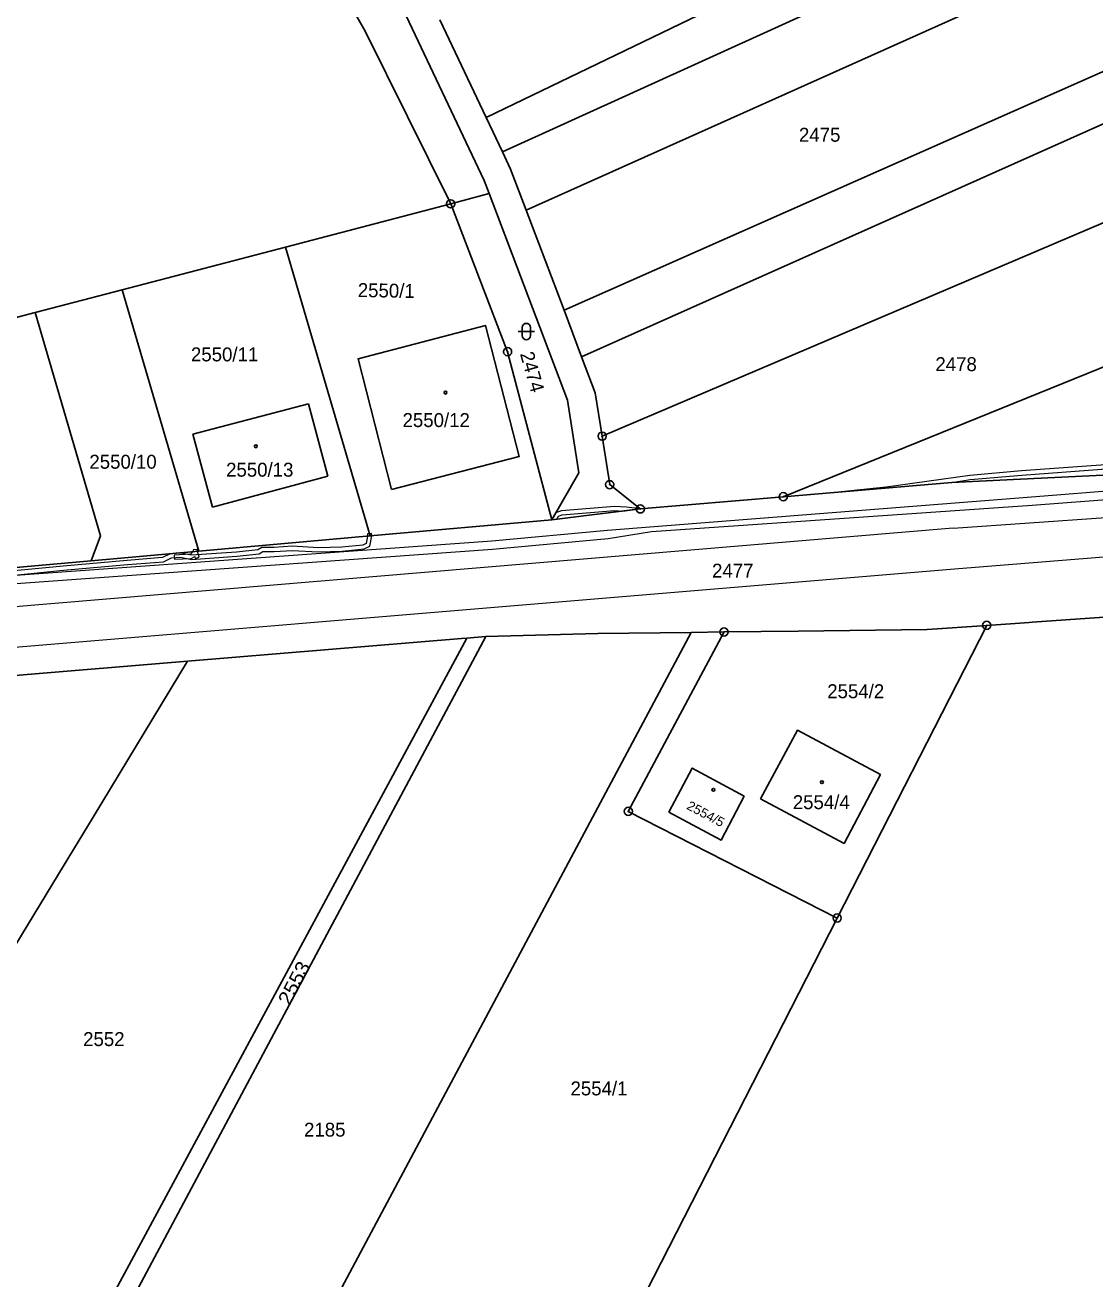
# Model space of a CAD drawing. Extents: x -606517 to -602431, y -1183120 to -1179397.
# Drawn here: x -605132.4 to -605001.8, y -1181010.4 to -1180857.3 of the extents above; entities that cross this region are included whole.
import ezdxf
from ezdxf.enums import TextEntityAlignment as Align

# ---------------------------------------------------------------- set-up
doc = ezdxf.new("R2010")
doc.units = 0
doc.header["$LTSCALE"] = 0.68
for name, color, linetype, lineweight in [('1', 7, 'Continuous', 25), ('13', 7, 'Continuous', 13), ('3', 7, 'Continuous', 25), ('4', 7, 'Continuous', 13), ('5', 7, 'Continuous', 25), ('8', 7, 'Continuous', 25)]:
    doc.layers.add(name, color=color, linetype=linetype, lineweight=lineweight)
doc.layers.add('2', color=7, linetype='Continuous')

msp = doc.modelspace()

# ---------------------------------------------------------------- linework, layer by layer
at = {"layer": '1'}
for p, q in [((-605076.11, -1180868.57), (-604959.12, -1180811.92)), ((-605074.12, -1180872.77), (-604955.31, -1180818.73)), ((-604951.69, -1180826.26), (-605071.22, -1180879.91)), ((-605101.48, -1180839.48), (-605090.87, -1180858.03)), ((-605066.61, -1180892.1), (-604946.99, -1180839.11)), ((-604945.04, -1180844.43), (-605064.46, -1180897.79)), ((-605076.35, -1180876.25), (-605090.81, -1180845.71)), ((-605081.76, -1180856.63), (-605076.11, -1180868.57)), ((-605061.96, -1180907.49), (-604942.1, -1180856.39)), ((-605090.87, -1180858.03), (-605080.53, -1180878.86)), ((-605074.12, -1180872.77), (-605076.11, -1180868.57)), ((-605073.13, -1180874.88), (-605074.12, -1180872.77)), ((-604937.14, -1180873.25), (-605039.85, -1180914.88)), ((-605071.22, -1180879.91), (-605073.13, -1180874.88)), ((-605075.74, -1180877.86), (-605076.35, -1180876.25)), ((-605080.44, -1180879.12), (-605075.74, -1180877.86)), ((-605066.19, -1180903.1), (-605075.74, -1180877.86)), ((-605080.53, -1180878.86), (-605080.44, -1180879.12)), ((-605080.44, -1180879.12), (-605073.5, -1180897.18)), ((-605071.22, -1180879.91), (-605066.61, -1180892.1)), ((-605100.61, -1180884.4), (-605120.54, -1180889.62)), ((-605120.54, -1180889.62), (-605131.18, -1180892.4)), ((-605131.18, -1180892.4), (-605153.68, -1180898.29)), ((-605064.46, -1180897.79), (-605066.61, -1180892.1)), ((-605073.5, -1180897.18), (-605068.11, -1180917.7)), ((-605064.46, -1180897.79), (-605062.79, -1180902.2)), ((-605062.79, -1180902.2), (-605061.96, -1180907.49)), ((-605097.8, -1180903.56), (-605111.9, -1180907.26)), ((-605095.45, -1180912.39), (-605097.8, -1180903.56)), ((-605064.8, -1180911.96), (-605066.19, -1180903.1)), ((-605111.9, -1180907.26), (-605109.53, -1180916.14)), ((-605061.03, -1180913.4), (-605061.96, -1180907.49)), ((-604991.55, -1180911.78), (-605019.29, -1180913.13)), ((-605109.53, -1180916.14), (-605095.45, -1180912.39)), ((-605068.11, -1180917.7), (-605064.8, -1180911.96)), ((-605057.3, -1180916.37), (-605061.03, -1180913.4)), ((-605019.29, -1180913.13), (-605039.85, -1180914.88)), ((-605039.85, -1180914.88), (-605057.3, -1180916.37)), ((-605068.11, -1180917.7), (-605057.3, -1180916.37)), ((-605090.27, -1180919.67), (-605068.11, -1180917.7)), ((-605124.32, -1180922.7), (-605111.18, -1180921.53)), ((-605148.55, -1180924.86), (-605124.32, -1180922.7)), ((-605015.01, -1180930.59), (-605009.83, -1180930.23)), ((-605009.83, -1180930.23), (-605009.45, -1180930.2)), ((-605009.45, -1180930.2), (-604990.65, -1180928.92)), ((-605116.76, -1181054.62), (-605051.07, -1180931.45)), ((-605062.49, -1180931.59), (-605076.15, -1180931.95)), ((-605051.07, -1180931.45), (-605062.49, -1180931.59)), ((-605051.07, -1180931.45), (-605047.08, -1180931.4)), ((-605047.08, -1180931.4), (-605038.03, -1180931.29)), ((-605038.03, -1180931.29), (-605022.3, -1180931.09)), ((-605033.27, -1180966.33), (-605015.01, -1180930.59)), ((-605022.3, -1180931.09), (-605015.01, -1180930.59)), ((-605078.46, -1180932.14), (-605138.39, -1181043.38)), ((-605076.15, -1180931.95), (-605136.19, -1181044.52)), ((-605112.56, -1180934.97), (-605079.11, -1180932.19)), ((-605079.11, -1180932.19), (-605078.46, -1180932.14)), ((-605076.21, -1180931.95), (-605078.46, -1180932.14)), ((-605076.15, -1180931.95), (-605076.21, -1180931.95)), ((-605133.61, -1180936.72), (-605112.56, -1180934.97)), ((-605112.56, -1180934.97), (-605124.1, -1180954)), ((-605124.1, -1180954), (-605128.32, -1180960.97)), ((-605128.32, -1180960.97), (-605169.43, -1181028.73)), ((-605085.89, -1181069.32), (-605033.27, -1180966.33))]:
    msp.add_line(p, q, dxfattribs=at)
for points in [[(-605080.44, -1180879.12), (-605100.61, -1180884.4), (-605090.27, -1180919.67)], [(-605120.54, -1180889.62), (-605111.18, -1180921.53), (-605090.27, -1180919.67)], [(-605131.18, -1180892.4), (-605123.19, -1180919.65), (-605124.32, -1180922.7)], [(-605047.08, -1180931.4), (-605058.76, -1180953.31), (-605033.27, -1180966.33)]]:
    msp.add_lwpolyline(points, dxfattribs=at)
for points in [[(-605087.65, -1180914), (-605091.75, -1180898.03), (-605076.19, -1180893.99), (-605072.09, -1180909.99)], [(-605042.63, -1180951.79), (-605038.11, -1180943.39), (-605027.98, -1180948.81), (-605032.43, -1180957.21)], [(-605053.8, -1180953.39), (-605050.96, -1180948.03), (-605044.62, -1180951.45), (-605047.42, -1180956.81)]]:
    msp.add_lwpolyline(points, close=True, dxfattribs=at)
at = {"layer": '13'}
for points in [[(-604965.16, -1180914.07), (-604966.44, -1180913.52), (-604975.42, -1180911.48), (-604982.15, -1180910.49), (-604988.28, -1180910.43), (-604999.37, -1180910.91), (-605010.75, -1180911.74), (-605017.08, -1180912.29), (-605027.29, -1180913.7), (-605032.77, -1180914.28), (-605019.29, -1180913.13), (-605017.02, -1180912.79), (-605010.71, -1180912.24), (-604999.35, -1180911.41), (-604988.28, -1180910.93), (-604982.19, -1180910.99), (-604975.52, -1180911.98), (-604966.58, -1180914), (-604965.71, -1180914.39)], [(-605057.3, -1180916.37), (-605058.97, -1180916.17), (-605060.43, -1180916.08), (-605066.93, -1180916.61), (-605067.63, -1180916.86), (-605068.11, -1180917.7), (-605067.49, -1180917.62), (-605067.29, -1180917.27), (-605066.83, -1180917.11), (-605060.43, -1180916.58), (-605059.49, -1180916.64)], [(-605090.58, -1180919.43), (-605090.58, -1180919.7), (-605090.27, -1180919.67), (-605090.35, -1180919.41)], [(-605090.35, -1180919.41), (-605090.27, -1180919.67), (-605090.07, -1180919.65), (-605090.09, -1180919.39)], [(-605111.35, -1180921.55), (-605111.92, -1180921.6), (-605112.19, -1180921.9), (-605114.18, -1180922), (-605114.16, -1180922.5), (-605112.13, -1180922.41), (-605111.68, -1180922.19), (-605111.62, -1180922.41), (-605111.14, -1180922.27)], [(-605111.92, -1180921.6), (-605111.35, -1180921.55), (-605111.37, -1180921.34), (-605111.87, -1180921.35)]]:
    msp.add_lwpolyline(points, close=True, dxfattribs=at)
for points in [[(-604998.29, -1180914.05), (-605009.54, -1180914.93), (-605061.31, -1180919), (-605075.44, -1180920.3), (-605155.59, -1180926.08), (-605179.81, -1180927.64), (-605194.41, -1180928.93), (-605194.33, -1180929.71), (-605155.53, -1180927.08), (-605075.34, -1180921.3), (-605061.23, -1180920), (-605055.93, -1180919.13), (-605009.47, -1180915.93), (-604998.24, -1180915.05)], [(-605134.08, -1180924.49), (-605127.69, -1180923.85), (-605119.91, -1180923.16), (-605115.49, -1180922.82), (-605114.54, -1180922.33), (-605113.42, -1180922.28), (-605112.1, -1180922.53), (-605106.54, -1180922.14), (-605103.81, -1180921.84), (-605103.36, -1180921.59), (-605101.98, -1180921.59), (-605099.8, -1180921.43), (-605096.57, -1180921.63), (-605093.71, -1180921.53), (-605091.01, -1180921.26), (-605090.31, -1180920.93), (-605090.07, -1180919.65), (-605090.27, -1180919.67), (-605090.58, -1180919.7), (-605090.75, -1180920.59), (-605091.15, -1180920.78), (-605093.75, -1180921.03), (-605096.57, -1180921.13), (-605099.8, -1180920.93), (-605102, -1180921.09), (-605103.48, -1180921.09), (-605103.97, -1180921.36), (-605106.58, -1180921.64), (-605112.08, -1180922.03), (-605113.57, -1180921.74), (-605114.68, -1180921.84), (-605115.63, -1180922.32), (-605119.95, -1180922.66), (-605127.73, -1180923.35), (-605134.14, -1180923.99)]]:
    msp.add_lwpolyline(points, dxfattribs=at)
at = {"layer": '3'}
for p, q in [((-605072.211, -1180894.711), (-605070.209, -1180894.711)), ((-605071.711, -1180894.211), (-605071.711, -1180895.212)), ((-605070.709, -1180895.212), (-605070.709, -1180894.211))]:
    msp.add_line(p, q, dxfattribs=at)
for centre, start, end in [((-605071.21, -1180894.2109), 0, 180), ((-605071.21, -1180895.2109), 180, 359.98789)]:
    msp.add_arc(centre, 0.5, start, end, dxfattribs=at)
at = {"layer": '4'}
for points in [[(-605019.1, -1180918.73), (-604991.17, -1180916.75), (-604982.34, -1180917.27), (-604968.84, -1180920.41), (-604955.87, -1180924.9), (-604868.36, -1180966.28)], [(-605019.1, -1180918.73), (-605180.25, -1180932.22), (-605225.75, -1180935.39), (-605261.87, -1180939.25), (-605283.98, -1180945.35), (-605296.94, -1180949.14)], [(-605262.69, -1180946.11), (-605224.79, -1180940.54), (-605180.08, -1180937.13), (-605018.93, -1180923.69), (-604991.13, -1180921.45)]]:
    msp.add_lwpolyline(points, dxfattribs=at)
at = {"layer": '5'}
for centre in [(-605081.0768, -1180902.1692), (-605104.2268, -1180908.7192), (-605035.1268, -1180949.7392), (-605048.3768, -1180950.6792)]:
    msp.add_circle(centre, 0.175, dxfattribs=at)
at = {"layer": '8'}
for centre, radius in [((-605080.44, -1180879.1199), 0.5), ((-605080.44, -1180879.1199), 0.0303), ((-605073.5, -1180897.1799), 0.5), ((-605073.5, -1180897.1799), 0.0303), ((-605061.96, -1180907.4899), 0.5), ((-605061.96, -1180907.4899), 0.0303), ((-605061.03, -1180913.3999), 0.5), ((-605061.03, -1180913.3999), 0.0303), ((-605039.85, -1180914.8799), 0.5), ((-605039.85, -1180914.8799), 0.0303), ((-605057.3, -1180916.3699), 0.5), ((-605057.3, -1180916.3699), 0.0303), ((-605015.01, -1180930.5899), 0.5), ((-605047.08, -1180931.3999), 0.5), ((-605047.08, -1180931.3999), 0.0303), ((-605015.01, -1180930.5899), 0.0303), ((-605058.76, -1180953.3099), 0.5), ((-605058.76, -1180953.3099), 0.0303), ((-605033.27, -1180966.3299), 0.5), ((-605033.27, -1180966.3299), 0.0303)]:
    msp.add_circle(centre, radius, dxfattribs=at)

# ---------------------------------------------------------------- texts
at = {"layer": '2'}
for s, p in [('2475', (-605037.93, -1180871.535)), ('2478', (-605021.28, -1180899.545)), ('2477', (-605048.54, -1180924.765)), ('2552', (-605125.31, -1180981.965)), ('2185', (-605098.34, -1180993.025))]:
    msp.add_text(s, height=1.7, dxfattribs=at).set_placement(p)
msp.add_text('2550/1', height=1.7, rotation=359, dxfattribs=at).set_placement((-605088.3198, -1180890.5546), align=Align.CENTER)
for s, p in [('2550/11', (-605108.039, -1180898.352)), ('2550/12', (-605082.209, -1180906.375)), ('2550/10', (-605120.439, -1180911.462)), ('2550/13', (-605103.749, -1180912.435)), ('2554/2', (-605031, -1180939.485)), ('2554/4', (-605035.21, -1180953.035)), ('2554/1', (-605062.34, -1180987.985))]:
    msp.add_text(s, height=1.7, dxfattribs=at).set_placement(p, align=Align.CENTER)
msp.add_text('2474', height=1.7, rotation=286, dxfattribs=at).set_placement((-605071.998, -1180897.437))
at = {"layer": '2', "width": 1.05}
msp.add_text('2554/5', height=1.139, rotation=332, dxfattribs=at).set_placement((-605049.5774, -1180954.1137), align=Align.CENTER)
at = {"layer": '2', "width": 1.1}
msp.add_text('2553', height=1.7, rotation=62, dxfattribs=at).set_placement((-605100.114, -1180977.119))

doc.saveas('drawing.dxf')
